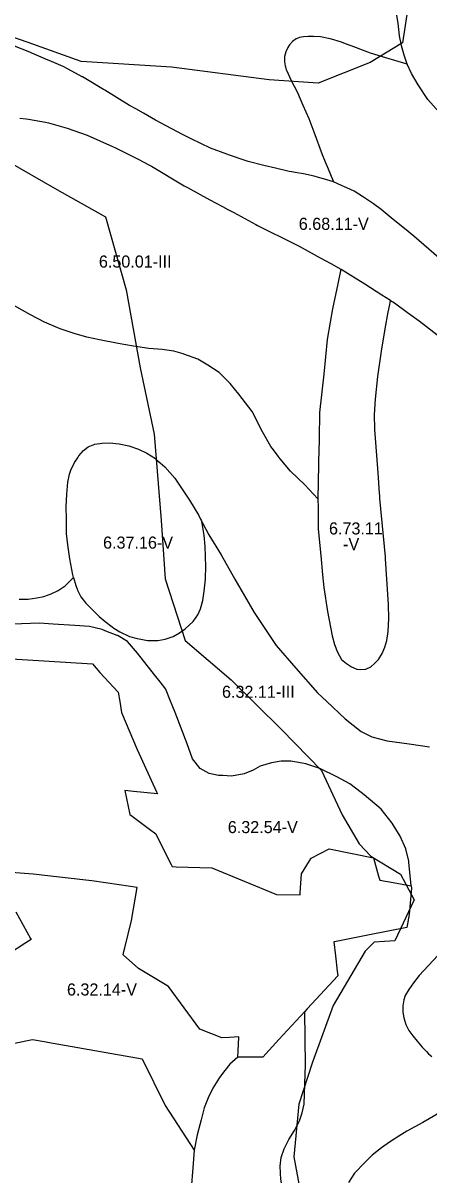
# Model space of a CAD drawing. Extents: x -555156 to -540209, y -1046851 to -1035695.
# Drawn here: x -542138 to -541802, y -1039776 to -1038823 of the extents above; entities that cross this region are included whole.
import ezdxf

# ---------------------------------------------------------------- set-up
doc = ezdxf.new("R2010")
doc.units = 0
for name, color, linetype in [('Vrstva 27', 7, 'Continuous'), ('Vrstva 28', 7, 'Continuous'), ('Vrstva 29', 7, 'Continuous')]:
    doc.layers.add(name, color=color, linetype=linetype)

msp = doc.modelspace()

# ---------------------------------------------------------------- linework, layer by layer
at = {"layer": 'Vrstva 28'}
for points in [[(-541829.01, -1038814.69), (-541827.82, -1038822.61), (-541826.47, -1038833.22), (-541824.99, -1038841.09), (-541822.75, -1038849.01), (-541821.92, -1038851.4), (-541820.47, -1038855.59), (-541820.06, -1038856.78)], [(-541820.06, -1038856.78), (-541837.65, -1038851.37), (-541850.23, -1038847.5), (-541864.15, -1038842.32), (-541872.33, -1038839.27), (-541874.3, -1038838.54), (-541877.08, -1038837.7), (-541880.69, -1038836.6), (-541883.86, -1038835.64), (-541891.8, -1038834.1), (-541897.69, -1038833.67), (-541902.02, -1038833.65), (-541905.86, -1038833.99), (-541909.28, -1038834.67), (-541911.92, -1038835.7), (-541915.08, -1038837.83), (-541917.55, -1038840.74), (-541918.92, -1038842.79), (-541920.54, -1038846.37), (-541921.48, -1038850.3), (-541921.57, -1038854.4), (-541921.53, -1038854.75), (-541921.14, -1038857.99), (-541920.88, -1038858.81), (-541920.12, -1038861.23), (-541919.93, -1038861.65), (-541918.66, -1038864.56), (-541916.32, -1038869.66), (-541910.94, -1038880.12), (-541906.31, -1038890.58), (-541901.53, -1038901.64), (-541897.35, -1038912.55), (-541890.33, -1038931.53), (-541889.26, -1038934.18), (-541884.17, -1038946.7), (-541881.14, -1038954.17)], [(-542038.56, -1038897.28), (-542044.8, -1038893.74), (-542050.07, -1038890.75), (-542070.46, -1038878.2), (-542071.47, -1038877.6), (-542084.96, -1038869.61), (-542089.02, -1038867.21), (-542089.23, -1038867.1), (-542100.72, -1038860.88), (-542104.97, -1038858.58), (-542116.73, -1038853.61), (-542120.13, -1038852.16), (-542121.34, -1038851.64), (-542130.98, -1038847.53), (-542132.67, -1038846.81), (-542146.79, -1038841.32)], [(-541618.18, -1039023.63), (-541636.21, -1039013.69), (-541655.82, -1039004.54), (-541674.38, -1038995.64), (-541682.91, -1038991.02), (-541689.47, -1038987.47), (-541716.14, -1038969.95), (-541734.69, -1038955.3), (-541752.21, -1038940.39), (-541765.14, -1038928), (-541768.25, -1038925.02), (-541770.77, -1038922.61), (-541787.76, -1038902.73), (-541788.67, -1038901.71), (-541802.88, -1038885.77), (-541810.95, -1038873.67), (-541816.47, -1038864.4), (-541820.06, -1038856.78)], [(-542140.77, -1038901.41), (-542135.65, -1038901.92), (-542133.83, -1038902.22), (-542119.7, -1038904.53), (-542117.27, -1038905.2), (-542101.67, -1038909.5), (-542085.2, -1038915.52), (-542064.02, -1038924.67), (-542061.61, -1038925.89), (-542042.22, -1038935.68), (-542034.49, -1038939.58), (-542031.88, -1038941.13), (-542004.69, -1038957.36), (-542001.97, -1038958.83), (-541983.4, -1038968.83), (-541972.89, -1038974.5), (-541968.55, -1038976.84), (-541963.73, -1038979.44), (-541945.27, -1038989.39), (-541944.04, -1038990.06), (-541912.79, -1039005.53), (-541909.44, -1039007.19), (-541891.93, -1039016.86), (-541883.26, -1039021.72), (-541875.01, -1039026.35)], [(-541881.14, -1038954.17), (-541889.35, -1038951.63), (-541893.44, -1038950.45), (-541897.12, -1038949.38), (-541905.93, -1038947.44), (-541912.84, -1038946.3), (-541915.49, -1038945.87), (-541917.73, -1038945.5), (-541928.94, -1038942.81), (-541938.83, -1038940.49), (-541951.83, -1038937.2), (-541955.02, -1038936.12), (-541967.21, -1038931.97), (-541969.48, -1038931.16), (-541983.04, -1038926.29), (-541998.88, -1038918.52), (-542006.03, -1038914.77), (-542028.38, -1038903.05), (-542038.56, -1038897.28)], [(-541785.47, -1039023.98), (-541814.49, -1038999.13), (-541822.29, -1038992.72), (-541831.7, -1038985.1), (-541841.41, -1038977.03), (-541847.98, -1038972.25), (-541856.04, -1038966.72), (-541863.96, -1038961.79), (-541869.86, -1038959), (-541871.88, -1038958.05), (-541874.29, -1038957.04), (-541881.14, -1038954.17)], [(-541875.01, -1039026.35), (-541877.49, -1039038.35), (-541881.77, -1039059.1), (-541883.69, -1039070.07), (-541886.21, -1039084.47), (-541889.09, -1039113.24), (-541892.49, -1039144.89), (-541892.92, -1039166.4), (-541893, -1039170.5), (-541893.06, -1039173.61), (-541893.07, -1039174.08)], [(-541833.74, -1039052.24), (-541840.96, -1039047.73), (-541855.07, -1039038.83), (-541874.68, -1039026.54), (-541875.01, -1039026.35)], [(-541966.55, -1039120.89), (-541975.81, -1039111.77), (-541985.07, -1039105.65), (-541993.44, -1039100.86), (-542005.09, -1039096.68), (-542005.7, -1039096.5), (-542009.49, -1039095.4), (-542013.31, -1039094.29), (-542022.87, -1039092.94), (-542034.07, -1039091.9), (-542046.65, -1039090.03), (-542059.35, -1039087.79), (-542075.03, -1039084.95), (-542085.49, -1039082.56), (-542095.79, -1039079.57), (-542107.59, -1039075.68), (-542120.44, -1039070.15), (-542131.94, -1039064.17), (-542143.44, -1039057.75), (-542168.66, -1039043.38)], [(-541854.24, -1039357.34), (-541850.21, -1039355.39), (-541846.92, -1039352.85), (-541843.78, -1039349.42), (-541840.65, -1039344.34), (-541838.41, -1039339.25), (-541836.76, -1039333.72), (-541835.72, -1039326.25), (-541835.27, -1039315.49), (-541835.57, -1039303.83), (-541837.95, -1039266.06), (-541838.06, -1039264.33), (-541842.5, -1039216.2), (-541842.54, -1039215.67), (-541842.69, -1039213.65), (-541842.82, -1039211.82), (-541844.06, -1039194.81), (-541846.69, -1039158.93), (-541846.75, -1039157.35), (-541846.87, -1039154.41), (-541847.01, -1039151.12), (-541847.18, -1039146.85), (-541846.13, -1039134.03), (-541844.3, -1039115.2), (-541841.16, -1039094.28), (-541838.29, -1039075.71), (-541835.62, -1039061.92), (-541834.39, -1039055.59), (-541833.74, -1039052.24)], [(-541833.74, -1039052.24), (-541830.5, -1039054.26), (-541830.45, -1039054.3), (-541819.72, -1039062.14), (-541810.11, -1039069.17), (-541785.8, -1039087.74)], [(-541893.92, -1039216.5), (-541904.64, -1039204.73), (-541916.66, -1039193.48), (-541925.29, -1039183.28), (-541926.93, -1039181.07), (-541929.9, -1039177.08), (-541931.9, -1039174.39), (-541932.87, -1039173.08), (-541939.93, -1039161.05), (-541948.33, -1039144.2), (-541959.53, -1039129.71), (-541966.55, -1039120.89)], [(-542096.52, -1039281.52), (-542096.94, -1039279.38), (-542099.56, -1039266.13), (-542101.2, -1039254.62), (-542102.1, -1039245.05), (-542102.19, -1039237.14), (-542102.22, -1039235.01), (-542102.24, -1039232.92), (-542102.54, -1039222.93), (-542101.95, -1039212.62), (-542101.05, -1039202.61), (-542099.71, -1039196.02), (-542098.36, -1039191.99), (-542097.1, -1039189.47), (-542095.52, -1039186.31), (-542094.31, -1039184.49), (-542092.6, -1039181.93), (-542091.94, -1039180.93), (-542088.2, -1039176.45), (-542084.32, -1039173.46), (-542078.79, -1039171.22), (-542072.82, -1039170.32), (-542066.55, -1039170.02), (-542058.48, -1039170.92), (-542050.71, -1039172.56), (-542042.65, -1039175.25), (-542035.63, -1039178.54), (-542028.46, -1039183.17), (-542027.81, -1039183.75), (-542024.57, -1039186.61), (-542020.89, -1039189.87), (-542020.69, -1039190.05), (-542012.47, -1039199.31), (-542000.34, -1039217.47), (-541992.72, -1039230.17), (-541991.15, -1039233.2), (-541990.35, -1039234.75), (-541990.11, -1039235.21)], [(-541893.07, -1039174.08), (-541893.92, -1039216.5)], [(-541893.92, -1039216.5), (-541893.83, -1039223.51), (-541893.8, -1039225.45), (-541893.77, -1039227.8), (-541893.58, -1039241.54), (-541891.49, -1039263.25), (-541890.06, -1039279.45), (-541889.14, -1039289.93), (-541886, -1039309.54), (-541882.08, -1039329.68), (-541880.08, -1039336.86), (-541877.69, -1039343.29), (-541874.26, -1039349.27), (-541870.37, -1039352.85), (-541866.04, -1039355.54), (-541861.71, -1039357.34), (-541858.42, -1039357.64), (-541854.24, -1039357.34)], [(-542026.66, -1039333.57), (-542020.54, -1039332.68), (-542013.97, -1039330.29), (-542008.59, -1039327.45), (-542003.96, -1039324.01), (-541997.24, -1039317.88), (-541993.35, -1039312.35), (-541991.26, -1039307.57), (-541989.17, -1039300.55), (-541988.13, -1039292.77), (-541987.1, -1039282.95), (-541986.97, -1039281.72), (-541986.82, -1039273.05), (-541986.97, -1039264.08), (-541987.42, -1039255.86), (-541988.16, -1039246.45), (-541989.83, -1039236.83), (-541990.11, -1039235.21)], [(-541990.11, -1039235.21), (-541989.28, -1039236.81), (-541984.36, -1039246.31), (-541974.2, -1039262.75), (-541962.84, -1039282.95), (-541946.74, -1039310.49), (-541928.44, -1039337.69), (-541912.24, -1039356.52), (-541894.2, -1039376.92), (-541886.48, -1039384.29), (-541871.46, -1039398.63), (-541858.13, -1039409.09), (-541849.27, -1039413.29), (-541836.47, -1039416.69), (-541818.43, -1039419.31), (-541801.44, -1039421.66)], [(-542141.33, -1039299.45), (-542134.01, -1039299.45), (-542126.69, -1039298.4), (-542121.02, -1039297.21), (-542114.89, -1039294.97), (-542109.07, -1039292.43), (-542103.39, -1039288.39), (-542096.52, -1039281.52)], [(-542096.52, -1039281.52), (-542094.48, -1039288.29), (-542092.83, -1039292.48), (-542090.29, -1039297.41), (-542086.26, -1039302.64), (-542081.63, -1039307.57), (-542075.21, -1039313.7), (-542070.13, -1039317.88), (-542064.46, -1039322.37), (-542062.96, -1039323.56), (-542058.03, -1039326.4), (-542050.11, -1039330.44), (-542043.69, -1039331.93), (-542043.54, -1039331.96), (-542035.03, -1039333.57), (-542026.66, -1039333.57)], [(-541816.57, -1039536.86), (-541818.49, -1039517.17), (-541818.58, -1039516.22), (-541821.19, -1039506.02), (-541825.9, -1039495.55), (-541831.54, -1039486.29), (-541832.43, -1039484.83), (-541841.58, -1039473.32), (-541855.7, -1039461.29), (-541857.96, -1039459.59), (-541867.46, -1039452.4), (-541878.18, -1039446.39), (-541892.29, -1039439.59), (-541904.06, -1039435.66), (-541907.1, -1039435.14), (-541916.34, -1039433.57), (-541919.27, -1039433.57), (-541924.44, -1039433.57), (-541932.29, -1039434.88), (-541941.7, -1039437.76), (-541947.71, -1039440.89), (-541955.03, -1039444.03), (-541965.58, -1039445.88), (-541972.83, -1039445.53), (-541975.4, -1039445.4), (-541976.3, -1039445.36), (-541984.14, -1039443.79), (-541991.46, -1039439.6), (-541997.73, -1039431.76), (-542002.18, -1039419.2), (-542012.27, -1039393.21), (-542014.1, -1039388.68), (-542016.6, -1039382.52), (-542019.7, -1039374.85), (-542020.05, -1039373.99), (-542024.71, -1039367.94), (-542029.2, -1039362.09), (-542043.38, -1039344.24), (-542051.81, -1039334.63), (-542059.45, -1039329.79), (-542059.65, -1039329.66), (-542060.25, -1039329.43), (-542069.65, -1039325.86), (-542072.72, -1039324.69), (-542083.18, -1039322.07), (-542095.46, -1039321.29), (-542113.24, -1039320.24), (-542124.74, -1039319.46), (-542162.43, -1039320.65)], [(-542175.22, -1039347.18), (-542080.59, -1039352.93), (-542074.72, -1039360.08), (-542059.37, -1039376.4), (-542058.12, -1039384.25), (-542056.68, -1039393.3), (-542043.65, -1039423.95), (-542027.66, -1039458.98), (-542026.96, -1039460.5), (-542046.76, -1039458.6), (-542053.78, -1039457.93), (-542049.79, -1039477.63), (-542047.74, -1039479.16), (-542033.52, -1039489.74), (-542028.29, -1039493.63), (-542016.8, -1039516.64), (-542015.57, -1039519.1), (-542014.75, -1039520.75), (-542011.28, -1039520.88), (-541981.89, -1039521.95), (-541928.3, -1039543.88), (-541908.7, -1039544.24), (-541908.59, -1039542.62), (-541907.49, -1039526.78), (-541900.97, -1039516.04), (-541899.59, -1039513.78), (-541884.67, -1039505.99), (-541847.8, -1039513.62), (-541843.6, -1039528.86), (-541842.73, -1039532.02), (-541831.56, -1039534.09), (-541816.57, -1039536.86)], [(-542055.23, -1039593.72), (-542054.62, -1039591.14), (-542053.91, -1039588.13), (-542048.51, -1039565.32), (-542043.67, -1039537.99), (-542058.56, -1039535.89), (-542081.23, -1039532.69), (-542086.22, -1039532.13), (-542129.93, -1039527.19), (-542183.68, -1039522.92)], [(-541816.57, -1039536.86), (-541816.29, -1039538.74), (-541818.2, -1039560.39), (-541820.33, -1039571.2), (-541851.23, -1039577.29), (-541880.31, -1039583.01), (-541880.84, -1039583.12), (-541879.4, -1039594.75), (-541877.86, -1039607.25), (-541877.36, -1039611.27), (-541902.76, -1039638.67), (-541904.65, -1039640.7)], [(-542144.12, -1039558.27), (-542131.95, -1039580.38), (-542131.57, -1039581.07), (-542135.92, -1039583.92), (-542150.99, -1039593.79)], [(-541960.29, -1039678.66), (-541959.51, -1039662.31), (-541959.48, -1039661.62), (-541967.16, -1039662.15), (-541973.42, -1039662.58), (-541991.74, -1039655.46), (-542017.62, -1039619.93), (-542042.66, -1039605.25), (-542055.23, -1039593.72)], [(-541794.56, -1039594.54), (-541809.96, -1039611.03), (-541814.65, -1039617.11), (-541818.68, -1039622.49), (-541821.52, -1039627.42), (-541822.86, -1039631.15), (-541823.46, -1039635.94), (-541823.61, -1039641.32), (-541822.86, -1039646.1), (-541821.07, -1039651.48), (-541818.53, -1039656.41), (-541815.39, -1039660.89), (-541811.81, -1039665.38), (-541807.48, -1039670.31), (-541804.05, -1039673.83), (-541802.25, -1039675.69), (-541799.58, -1039678.06)], [(-541904.65, -1039640.7), (-541926.23, -1039663.99), (-541939.68, -1039678.49), (-541960.29, -1039678.66)], [(-541895.16, -1039834.05), (-541906.66, -1039815.74), (-541914.31, -1039804.08), (-541917.9, -1039798.1), (-541921.04, -1039791.98), (-541923.13, -1039786.89), (-541924.32, -1039781.66), (-541924.61, -1039778.6), (-541924.92, -1039775.39), (-541924.97, -1039774.19), (-541925.22, -1039768.66), (-541924.32, -1039761.64), (-541921.93, -1039754.46), (-541917.9, -1039746.69), (-541913.27, -1039739.37), (-541909.09, -1039731.3), (-541907, -1039724.57), (-541905.35, -1039717.4), (-541904.56, -1039692.35), (-541904.34, -1039685.44), (-541904.65, -1039640.7)], [(-542161.9, -1039670.27), (-542130.45, -1039663.89), (-542119.17, -1039665.9), (-542117.97, -1039666.11), (-542039.62, -1039680.05), (-542020.59, -1039718.44), (-541996.59, -1039755.61)], [(-541960.29, -1039678.66), (-541966.97, -1039684.29), (-541971.12, -1039689.68), (-541975.48, -1039695.34), (-541981.01, -1039704.16), (-541984.89, -1039712.08), (-541988.18, -1039720.6), (-541990.72, -1039730.47), (-541994.01, -1039742.87), (-541996.59, -1039755.61)], [(-541793.1, -1039724.67), (-541806.99, -1039732.74), (-541820.14, -1039739.89), (-541826.93, -1039744.08), (-541834.51, -1039748.78), (-541841.31, -1039753.49), (-541848.89, -1039759.77), (-541855.17, -1039765.78), (-541863.53, -1039774.68), (-541868.58, -1039782.43)], [(-541996.59, -1039755.61), (-541997.65, -1039770.29), (-541998.87, -1039787.19), (-542000.37, -1039807.87), (-541997.75, -1039831.11), (-541994.33, -1039836.86), (-541985.97, -1039839.17), (-541983.75, -1039869.57), (-542001.55, -1039871.8), (-542007.42, -1039879.17), (-542022.88, -1039898.58), (-542023.8, -1039899.74), (-542004.85, -1039922.06), (-541996.97, -1039931.34), (-541995.71, -1039947.75), (-541995.59, -1039949.36), (-541994.6, -1039962.18), (-541992.12, -1039973.6), (-541991.39, -1039976.96)]]:
    msp.add_lwpolyline(points, dxfattribs=at)
at = {"layer": 'Vrstva 29'}
for points in [[(-542144.947999, -1038616.525994), (-542097.625008, -1038616.801008), (-542052.374005, -1038623.731), (-542014.545001, -1038628.497997), (-541977.588007, -1038629.837001), (-541946.980992, -1038639.366998), (-541917.569001, -1038654.635003), (-541885.324999, -1038674.074998), (-541858.597002, -1038698.992999), (-541841.354004, -1038734.796007), (-541830.606992, -1038775.704995), (-541818.701997, -1038804.734996), (-541823.790995, -1038838.897997), (-541850.582003, -1038855.389003), (-541893.826996, -1038872.474003), (-541934.449992, -1038869.675), (-542015.347995, -1038859.004998), (-542090.061992, -1038854.440997), (-542134.010001, -1038838.718006), (-542179.028999, -1038823.378996)], [(-542152.490993, -1038935.965005), (-542110.349997, -1038960.420009), (-542070.046994, -1038983.122999), (-542052.906995, -1039043.455994), (-542041.132996, -1039108.008003), (-542029.734007, -1039162.799005), (-542023.906998, -1039234.310992), (-542020.428998, -1039282.534008), (-542003.977003, -1039333.581998), (-541965.884001, -1039366.247002), (-541924.176992, -1039407.267995), (-541890.865998, -1039441.407991), (-541873.714008, -1039477.967006), (-541859.665008, -1039501.883991), (-541850.184867, -1039512.146799)], [(-541850.184867, -1039512.146799), (-541825.51, -1039527.09), (-541814.2, -1039548.41), (-541830.29, -1039582.16), (-541847.248747, -1039583.4265), (-541854.897993, -1039590.909993), (-541881.233003, -1039635.832992), (-541898.318997, -1039682.625995), (-541909.615005, -1039717.326996), (-541913.793995, -1039761.056997), (-541908.776002, -1039787.732003)]]:
    msp.add_lwpolyline(points, dxfattribs=at)

# ---------------------------------------------------------------- texts
at = {"layer": 'Vrstva 27'}
for s, p in [('6.68.11-V', (-541909.780576, -1038993.79)), ('6.50.01-III', (-542075.396548, -1039025.01)), ('6.73.11', (-541884.743394, -1039245.91)), ('6.37.16-V', (-542071.937974, -1039257.65)), ('-V', (-541873.047227, -1039258.91)), ('6.32.11-III', (-541973.396548, -1039381.13)), ('6.32.54-V', (-541968.570884, -1039493.11)), ('6.32.14-V', (-542101.840884, -1039627.52))]:
    msp.add_text(s, height=10, dxfattribs=at).set_placement(p)

doc.saveas('drawing.dxf')
